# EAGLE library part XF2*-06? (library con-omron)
OMRON FPC Connector Source : http://www.omron.com/ecb/products/pdf/fpc.pdf
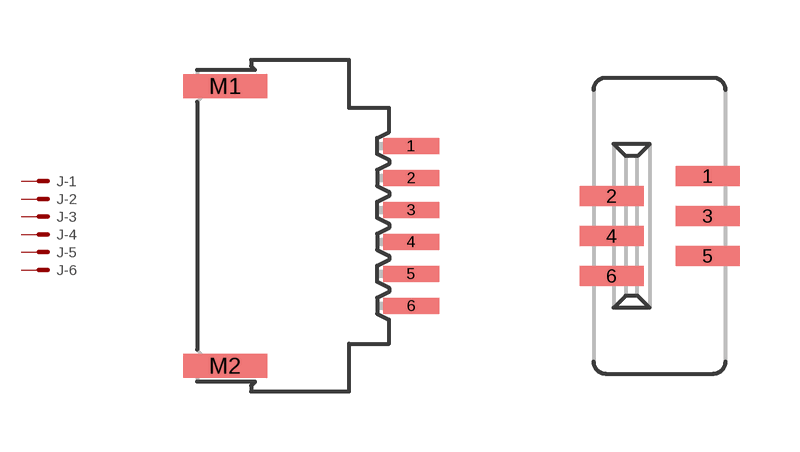
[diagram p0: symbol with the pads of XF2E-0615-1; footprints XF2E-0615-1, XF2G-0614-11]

Designator prefix J; gates -1=P -2=P -3=P -4=P -5=P -6=P

## XF2E-0615-1 (OC_FARNELL: unknown; OC_NEWARK: unknown)  [XF2E-0615-1]
1  -1:MS  pas
2  -2:MS  pas
3  -3:MS  pas
4  -4:MS  pas
5  -5:MS  pas
6  -6:MS  pas

## XF2G-0614-11 (MF: OMRON COMPONENTS USA; MPN: XF2G-0614-11; OC_FARNELL: unknown; OC_NEWARK: 89C8494)  [XF2G-0614-11]
Pads as for XF2E-0615-1

## XF2J-0624-11 (MPN: XF2J-0624-11; OC_FARNELL: 1430935; OC_NEWARK: 37M0807)  [XF2J-0624-11]
Pads as for XF2E-0615-1

## XF2L-0625-1 (MF: OMRON COMPONENTS USA; MPN: XF2L-0625-1; OC_FARNELL: 1536105; OC_NEWARK: 29C7842)  [XF2L-0625-1]
Pads as for XF2E-0615-1

## XF2L-0635-1 (MPN: XF2L-0635-1; OC_FARNELL: unknown; OC_NEWARK: 05M1986)  [XF2L-0635-1]
Pads as for XF2E-0615-1

## XF2R-0615-4A (MPN: XF2R-0615-4A; OC_FARNELL: unknown; OC_NEWARK: 37M0943)  [XF2R-0615-4A]
Pads as for XF2E-0615-1

## Footprint XF2E-0615-1 (pad centres in mm)
Non-ZIF Type (0.8 mm-pitch) Source : http://www.omron.com/ecb/products/pdf/fpc.pdf
smd 1.4 x 0.4: 1 2.54,2; 2 2.54,1.2; 3 2.54,0.4; 4 2.54,-0.4; 5 2.54,-1.2; 6 2.54,-2
smd 2.1 x 0.6: M1 -2.11,3.5; M2 -2.11,-3.5

## Footprint XF2G-0614-11 (pad centres in mm)
Non-ZIF Type (0.5 mm-pitch) Source : http://www.omron.com/ecb/products/pdf/fpc.pdf
smd 1.6 x 0.5: 1 1.2,1.25; 2 -1.2,0.75; 3 1.2,0.25; 4 -1.2,-0.25; 5 1.2,-0.75; 6 -1.2,-1.25

## Footprint XF2J-0624-11 (pad centres in mm)
ZIF Slide-locking Type (0.5 mm-pitch) Standard Source : http://www.omron.com/ecb/products/pdf/fpc.pdf
smd 1.6 x 0.5: 1 1.2,1.25; 2 -1.2,0.75; 3 1.2,0.25; 4 -1.2,-0.25; 5 1.2,-0.75; 6 -1.2,-1.25
smd 2.9 x 1.4: M1 0,2.95; M2 0,-2.95

## Footprint XF2L-0625-1 (pad centres in mm)
ZIF Slide-locking Type (0.5 mm-pitch) Upper-contact Type Source : http://www.omron.com/ecb/products/pdf/fpc.pdf
smd 1 x 0.25: 1 1.905,1.25; 2 1.905,0.75; 3 1.905,0.25; 4 1.905,-0.25; 5 1.905,-0.75; 6 1.905,-1.25
smd 1.34 x 1: M1 0.18,3.638; M2 0.18,-3.638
